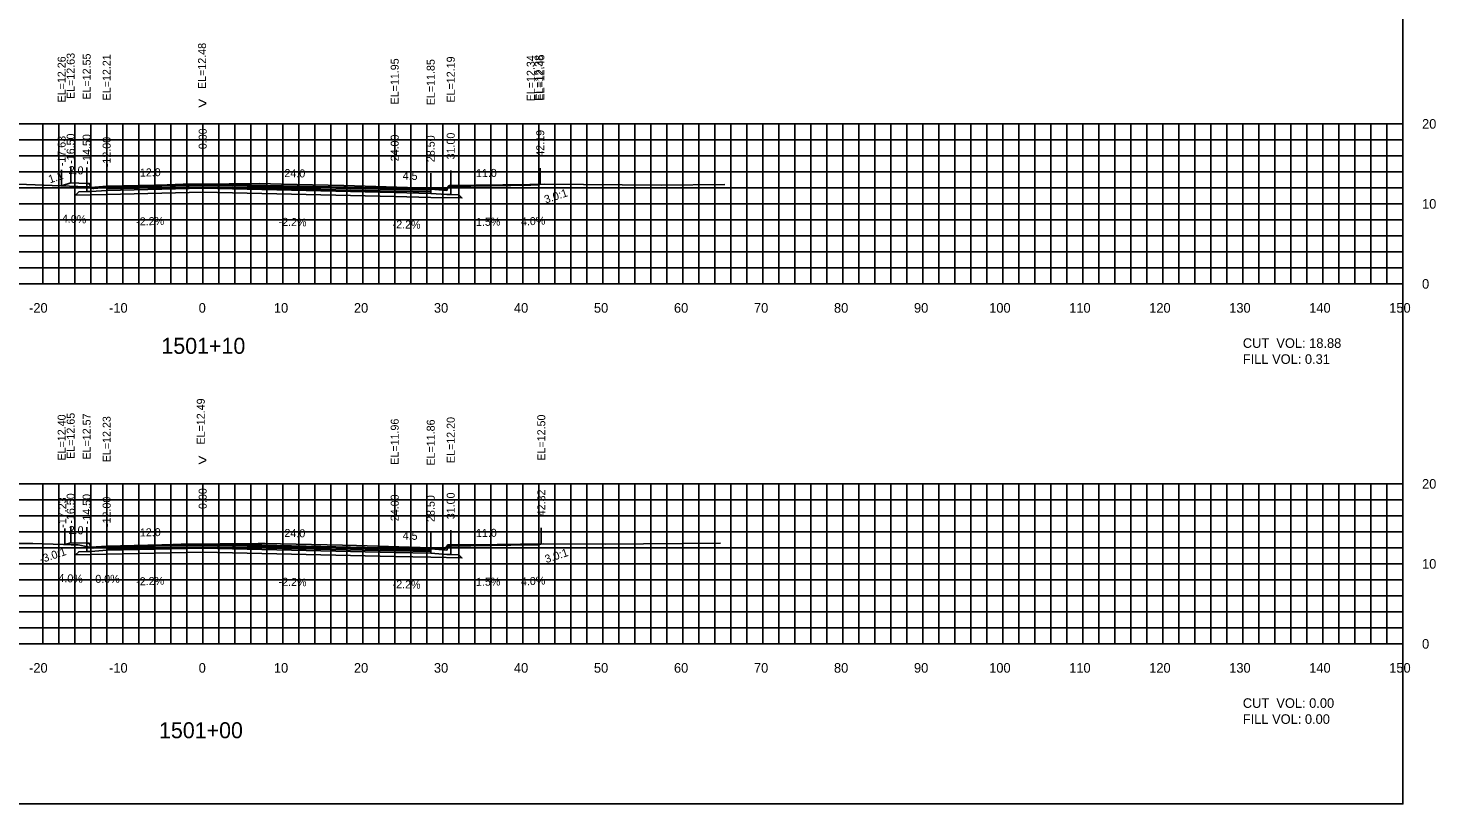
# Model space of a CAD drawing. Extents: x 1800674 to 1802785, y 250079 to 250269.
# Drawn here: x 1802269.2 to 1802445.1, y 250079.4 to 250176.4 of the extents above; entities that cross this region are included whole.
import ezdxf

# ---------------------------------------------------------------- set-up
doc = ezdxf.new("R2010")
doc.units = 0
for name, color, linetype in [('1', 7, 'Continuous'), ('10', 7, 'Continuous'), ('3', 7, 'Continuous'), ('31', 7, 'Continuous'), ('4', 7, 'Continuous'), ('60', 7, 'Continuous'), ('ANNO-TXT', 7, 'Continuous'), ('BASE', 7, 'Continuous'), ('CL-CNST', 7, 'Continuous'), ('Level 62', 7, 'Continuous'), ('LOWER BINDER', 7, 'Continuous'), ('M-ROADS', 7, 'Continuous'), ('UPPER BINDER', 7, 'Continuous'), ('WEARING', 7, 'Continuous')]:
    doc.layers.add(name, color=color, linetype=linetype)

msp = doc.modelspace()

# ---------------------------------------------------------------- linework, layer by layer
for p, q in [((1802273.37, 250156.69), (1802273.37, 250158.69)), ((1802274.5, 250157.07), (1802274.5, 250159.07)), ((1802276.5, 250156.99), (1802276.5, 250158.99)), ((1802279, 250156.65), (1802279, 250158.65)), ((1802291, 250156.91), (1802291, 250158.91)), ((1802315, 250156.38), (1802315, 250158.38)), ((1802319.5, 250156.28), (1802319.5, 250158.28)), ((1802322, 250156.62), (1802322, 250158.62)), ((1802333.19, 250156.88), (1802333.19, 250158.88)), ((1802273.77, 250111.84), (1802273.77, 250113.84)), ((1802274.5, 250112.08), (1802274.5, 250114.08)), ((1802276.5, 250112), (1802276.5, 250114)), ((1802279, 250111.66), (1802279, 250113.66)), ((1802291, 250111.92), (1802291, 250113.92)), ((1802333.32, 250111.93), (1802333.32, 250113.93)), ((1802315, 250111.39), (1802315, 250113.39)), ((1802319.5, 250111.3), (1802319.5, 250113.3)), ((1802322, 250111.64), (1802322, 250113.64))]:
    msp.add_line(p, q)
for points in [[(1802141, 250079.43), (1802441, 250079.43), (1802441, 250269.43), (1802141, 250269.43)], [(1802279, 250156.65), (1802277, 250156.49), (1802276.83, 250156.99), (1802276.5, 250156.99), (1802276.5, 250155.96), (1802277, 250155.96), (1802279, 250156.12)], [(1802319.5, 250156.28), (1802321.5, 250156.12), (1802321.67, 250156.62), (1802322, 250156.62), (1802322, 250155.59), (1802321.5, 250155.59), (1802319.5, 250155.75)], [(1802279, 250111.66), (1802277, 250111.5), (1802276.83, 250112), (1802276.5, 250112), (1802276.5, 250110.97), (1802277, 250110.97), (1802279, 250111.13)], [(1802319.5, 250111.3), (1802321.5, 250111.14), (1802321.67, 250111.64), (1802322, 250111.64), (1802322, 250110.61), (1802321.5, 250110.61), (1802319.5, 250110.77)]]:
    msp.add_lwpolyline(points, close=True)
at = {"layer": '60'}
for p, q in [((1802441, 250144.43), (1802441, 250164.43)), ((1802441.06, 250164.43), (1802441, 250164.43)), ((1802441.06, 250154.43), (1802441, 250154.43)), ((1802141, 250144.43), (1802441, 250144.43)), ((1802271, 250144.37), (1802271, 250144.43)), ((1802281, 250144.37), (1802281, 250144.43)), ((1802291, 250144.37), (1802291, 250144.43)), ((1802301, 250144.37), (1802301, 250144.43)), ((1802311, 250144.37), (1802311, 250144.43)), ((1802321, 250144.37), (1802321, 250144.43)), ((1802331, 250144.37), (1802331, 250144.43)), ((1802341, 250144.37), (1802341, 250144.43)), ((1802351, 250144.37), (1802351, 250144.43)), ((1802361, 250144.37), (1802361, 250144.43)), ((1802371, 250144.37), (1802371, 250144.43)), ((1802381, 250144.37), (1802381, 250144.43)), ((1802391, 250144.37), (1802391, 250144.43)), ((1802401, 250144.37), (1802401, 250144.43)), ((1802411, 250144.37), (1802411, 250144.43)), ((1802421, 250144.37), (1802421, 250144.43)), ((1802431, 250144.37), (1802431, 250144.43)), ((1802441, 250144.37), (1802441, 250144.43)), ((1802441.06, 250144.43), (1802441, 250144.43)), ((1802441, 250099.43), (1802441, 250119.43)), ((1802441.06, 250119.43), (1802441, 250119.43)), ((1802441.06, 250109.43), (1802441, 250109.43)), ((1802141, 250099.43), (1802441, 250099.43)), ((1802271, 250099.37), (1802271, 250099.43)), ((1802281, 250099.37), (1802281, 250099.43)), ((1802291, 250099.37), (1802291, 250099.43)), ((1802301, 250099.37), (1802301, 250099.43)), ((1802311, 250099.37), (1802311, 250099.43)), ((1802321, 250099.37), (1802321, 250099.43)), ((1802331, 250099.37), (1802331, 250099.43)), ((1802341, 250099.37), (1802341, 250099.43)), ((1802351, 250099.37), (1802351, 250099.43)), ((1802361, 250099.37), (1802361, 250099.43)), ((1802371, 250099.37), (1802371, 250099.43)), ((1802381, 250099.37), (1802381, 250099.43)), ((1802391, 250099.37), (1802391, 250099.43)), ((1802401, 250099.37), (1802401, 250099.43)), ((1802411, 250099.37), (1802411, 250099.43)), ((1802421, 250099.37), (1802421, 250099.43)), ((1802431, 250099.37), (1802431, 250099.43)), ((1802441, 250099.37), (1802441, 250099.43)), ((1802441.06, 250099.43), (1802441, 250099.43))]:
    msp.add_line(p, q, dxfattribs=at)
at = {"layer": 'BASE'}
for points in [[(1802319.5, 250155.25), (1802323.4, 250155.17), (1802323, 250155.57), (1802322, 250155.59), (1802321.5, 250155.59), (1802319.5, 250155.75), (1802315, 250155.85), (1802291, 250156.38), (1802279, 250156.12), (1802277, 250155.96), (1802276.5, 250155.96), (1802275.5, 250155.93), (1802275.1, 250155.53), (1802279, 250155.62), (1802291, 250155.88), (1802315, 250155.35)], [(1802319.5, 250110.27), (1802323.4, 250110.18), (1802323, 250110.58), (1802322, 250110.61), (1802321.5, 250110.61), (1802319.5, 250110.77), (1802315, 250110.86), (1802291, 250111.39), (1802279, 250111.13), (1802277, 250110.97), (1802276.5, 250110.97), (1802275.5, 250110.95), (1802275.1, 250110.54), (1802279, 250110.63), (1802291, 250110.89), (1802315, 250110.36)]]:
    msp.add_lwpolyline(points, close=True, dxfattribs=at)
at = {"layer": 'CL-CNST'}
for points in [[(1802273.37, 250156.69), (1802274.5, 250157.07), (1802276.5, 250156.99), (1802276.83, 250156.99), (1802277, 250156.49), (1802279, 250156.65), (1802291, 250156.91), (1802315, 250156.38), (1802319.5, 250156.28), (1802321.5, 250156.12), (1802321.67, 250156.62), (1802322, 250156.62), (1802332, 250156.77), (1802333, 250156.81), (1802333.19, 250156.88)], [(1802273.77, 250111.84), (1802274.5, 250112.08), (1802276.5, 250112), (1802276.83, 250112), (1802277, 250111.5), (1802279, 250111.66), (1802291, 250111.92), (1802315, 250111.39), (1802319.5, 250111.3), (1802321.5, 250111.14), (1802321.67, 250111.64), (1802322, 250111.64), (1802332, 250111.79), (1802333, 250111.83), (1802333.32, 250111.93)]]:
    msp.add_lwpolyline(points, dxfattribs=at)
at = {"layer": 'Level 62'}
for p, q in [((1802141, 250164.43), (1802441, 250164.43)), ((1802271, 250144.43), (1802271, 250164.43)), ((1802273, 250144.43), (1802273, 250164.43)), ((1802275, 250144.43), (1802275, 250164.43)), ((1802277, 250144.43), (1802277, 250164.43)), ((1802279, 250144.43), (1802279, 250164.43)), ((1802281, 250144.43), (1802281, 250164.43)), ((1802283, 250144.43), (1802283, 250164.43)), ((1802285, 250144.43), (1802285, 250164.43)), ((1802287, 250144.43), (1802287, 250164.43)), ((1802289, 250144.43), (1802289, 250164.43)), ((1802291, 250144.43), (1802291, 250164.43)), ((1802293, 250144.43), (1802293, 250164.43)), ((1802295, 250144.43), (1802295, 250164.43)), ((1802297, 250144.43), (1802297, 250164.43)), ((1802299, 250144.43), (1802299, 250164.43)), ((1802301, 250144.43), (1802301, 250164.43)), ((1802303, 250144.43), (1802303, 250164.43)), ((1802305, 250144.43), (1802305, 250164.43)), ((1802307, 250144.43), (1802307, 250164.43)), ((1802309, 250144.43), (1802309, 250164.43)), ((1802311, 250144.43), (1802311, 250164.43)), ((1802313, 250144.43), (1802313, 250164.43)), ((1802315, 250144.43), (1802315, 250164.43)), ((1802317, 250144.43), (1802317, 250164.43)), ((1802319, 250144.43), (1802319, 250164.43)), ((1802321, 250144.43), (1802321, 250164.43)), ((1802323, 250144.43), (1802323, 250164.43)), ((1802325, 250144.43), (1802325, 250164.43)), ((1802327, 250144.43), (1802327, 250164.43)), ((1802329, 250144.43), (1802329, 250164.43)), ((1802331, 250144.43), (1802331, 250164.43)), ((1802333, 250144.43), (1802333, 250164.43)), ((1802335, 250144.43), (1802335, 250164.43)), ((1802337, 250144.43), (1802337, 250164.43)), ((1802339, 250144.43), (1802339, 250164.43)), ((1802341, 250144.43), (1802341, 250164.43)), ((1802343, 250144.43), (1802343, 250164.43)), ((1802345, 250144.43), (1802345, 250164.43)), ((1802347, 250144.43), (1802347, 250164.43)), ((1802349, 250144.43), (1802349, 250164.43)), ((1802351, 250144.43), (1802351, 250164.43)), ((1802353, 250144.43), (1802353, 250164.43)), ((1802355, 250144.43), (1802355, 250164.43)), ((1802357, 250144.43), (1802357, 250164.43)), ((1802359, 250144.43), (1802359, 250164.43)), ((1802361, 250144.43), (1802361, 250164.43)), ((1802363, 250144.43), (1802363, 250164.43)), ((1802365, 250144.43), (1802365, 250164.43)), ((1802367, 250144.43), (1802367, 250164.43)), ((1802369, 250144.43), (1802369, 250164.43)), ((1802371, 250144.43), (1802371, 250164.43)), ((1802373, 250144.43), (1802373, 250164.43)), ((1802375, 250144.43), (1802375, 250164.43)), ((1802377, 250144.43), (1802377, 250164.43)), ((1802379, 250144.43), (1802379, 250164.43)), ((1802381, 250144.43), (1802381, 250164.43)), ((1802383, 250144.43), (1802383, 250164.43)), ((1802385, 250144.43), (1802385, 250164.43)), ((1802387, 250144.43), (1802387, 250164.43)), ((1802389, 250144.43), (1802389, 250164.43)), ((1802391, 250144.43), (1802391, 250164.43)), ((1802393, 250144.43), (1802393, 250164.43)), ((1802395, 250144.43), (1802395, 250164.43)), ((1802397, 250144.43), (1802397, 250164.43)), ((1802399, 250144.43), (1802399, 250164.43)), ((1802401, 250144.43), (1802401, 250164.43)), ((1802403, 250144.43), (1802403, 250164.43)), ((1802405, 250144.43), (1802405, 250164.43)), ((1802407, 250144.43), (1802407, 250164.43)), ((1802409, 250144.43), (1802409, 250164.43)), ((1802411, 250144.43), (1802411, 250164.43)), ((1802413, 250144.43), (1802413, 250164.43)), ((1802415, 250144.43), (1802415, 250164.43)), ((1802417, 250144.43), (1802417, 250164.43)), ((1802419, 250144.43), (1802419, 250164.43)), ((1802421, 250144.43), (1802421, 250164.43)), ((1802423, 250144.43), (1802423, 250164.43)), ((1802425, 250144.43), (1802425, 250164.43)), ((1802427, 250144.43), (1802427, 250164.43)), ((1802429, 250144.43), (1802429, 250164.43)), ((1802431, 250144.43), (1802431, 250164.43)), ((1802433, 250144.43), (1802433, 250164.43)), ((1802435, 250144.43), (1802435, 250164.43)), ((1802437, 250144.43), (1802437, 250164.43)), ((1802439, 250144.43), (1802439, 250164.43)), ((1802441, 250144.43), (1802441, 250164.43)), ((1802141, 250162.43), (1802441, 250162.43)), ((1802141, 250160.43), (1802441, 250160.43)), ((1802141, 250158.43), (1802441, 250158.43)), ((1802141, 250156.43), (1802441, 250156.43)), ((1802141, 250154.43), (1802441, 250154.43)), ((1802141, 250152.43), (1802441, 250152.43)), ((1802141, 250150.43), (1802441, 250150.43)), ((1802141, 250148.43), (1802441, 250148.43)), ((1802141, 250146.43), (1802441, 250146.43)), ((1802141, 250144.43), (1802441, 250144.43)), ((1802141, 250119.43), (1802441, 250119.43)), ((1802271, 250099.43), (1802271, 250119.43)), ((1802273, 250099.43), (1802273, 250119.43)), ((1802275, 250099.43), (1802275, 250119.43)), ((1802277, 250099.43), (1802277, 250119.43)), ((1802279, 250099.43), (1802279, 250119.43)), ((1802281, 250099.43), (1802281, 250119.43)), ((1802283, 250099.43), (1802283, 250119.43)), ((1802285, 250099.43), (1802285, 250119.43)), ((1802287, 250099.43), (1802287, 250119.43)), ((1802289, 250099.43), (1802289, 250119.43)), ((1802291, 250099.43), (1802291, 250119.43)), ((1802293, 250099.43), (1802293, 250119.43)), ((1802295, 250099.43), (1802295, 250119.43)), ((1802297, 250099.43), (1802297, 250119.43)), ((1802299, 250099.43), (1802299, 250119.43)), ((1802301, 250099.43), (1802301, 250119.43)), ((1802303, 250099.43), (1802303, 250119.43)), ((1802305, 250099.43), (1802305, 250119.43)), ((1802307, 250099.43), (1802307, 250119.43)), ((1802309, 250099.43), (1802309, 250119.43)), ((1802311, 250099.43), (1802311, 250119.43)), ((1802313, 250099.43), (1802313, 250119.43)), ((1802315, 250099.43), (1802315, 250119.43)), ((1802317, 250099.43), (1802317, 250119.43)), ((1802319, 250099.43), (1802319, 250119.43)), ((1802321, 250099.43), (1802321, 250119.43)), ((1802323, 250099.43), (1802323, 250119.43)), ((1802325, 250099.43), (1802325, 250119.43)), ((1802327, 250099.43), (1802327, 250119.43)), ((1802329, 250099.43), (1802329, 250119.43)), ((1802331, 250099.43), (1802331, 250119.43)), ((1802333, 250099.43), (1802333, 250119.43)), ((1802335, 250099.43), (1802335, 250119.43)), ((1802337, 250099.43), (1802337, 250119.43)), ((1802339, 250099.43), (1802339, 250119.43)), ((1802341, 250099.43), (1802341, 250119.43)), ((1802343, 250099.43), (1802343, 250119.43)), ((1802345, 250099.43), (1802345, 250119.43)), ((1802347, 250099.43), (1802347, 250119.43)), ((1802349, 250099.43), (1802349, 250119.43)), ((1802351, 250099.43), (1802351, 250119.43)), ((1802353, 250099.43), (1802353, 250119.43)), ((1802355, 250099.43), (1802355, 250119.43)), ((1802357, 250099.43), (1802357, 250119.43)), ((1802359, 250099.43), (1802359, 250119.43)), ((1802361, 250099.43), (1802361, 250119.43)), ((1802363, 250099.43), (1802363, 250119.43)), ((1802365, 250099.43), (1802365, 250119.43)), ((1802367, 250099.43), (1802367, 250119.43)), ((1802369, 250099.43), (1802369, 250119.43)), ((1802371, 250099.43), (1802371, 250119.43)), ((1802373, 250099.43), (1802373, 250119.43)), ((1802375, 250099.43), (1802375, 250119.43)), ((1802377, 250099.43), (1802377, 250119.43)), ((1802379, 250099.43), (1802379, 250119.43)), ((1802381, 250099.43), (1802381, 250119.43)), ((1802383, 250099.43), (1802383, 250119.43)), ((1802385, 250099.43), (1802385, 250119.43)), ((1802387, 250099.43), (1802387, 250119.43)), ((1802389, 250099.43), (1802389, 250119.43)), ((1802391, 250099.43), (1802391, 250119.43)), ((1802393, 250099.43), (1802393, 250119.43)), ((1802395, 250099.43), (1802395, 250119.43)), ((1802397, 250099.43), (1802397, 250119.43)), ((1802399, 250099.43), (1802399, 250119.43)), ((1802401, 250099.43), (1802401, 250119.43)), ((1802403, 250099.43), (1802403, 250119.43)), ((1802405, 250099.43), (1802405, 250119.43)), ((1802407, 250099.43), (1802407, 250119.43)), ((1802409, 250099.43), (1802409, 250119.43)), ((1802411, 250099.43), (1802411, 250119.43)), ((1802413, 250099.43), (1802413, 250119.43)), ((1802415, 250099.43), (1802415, 250119.43)), ((1802417, 250099.43), (1802417, 250119.43)), ((1802419, 250099.43), (1802419, 250119.43)), ((1802421, 250099.43), (1802421, 250119.43)), ((1802423, 250099.43), (1802423, 250119.43)), ((1802425, 250099.43), (1802425, 250119.43)), ((1802427, 250099.43), (1802427, 250119.43)), ((1802429, 250099.43), (1802429, 250119.43)), ((1802431, 250099.43), (1802431, 250119.43)), ((1802433, 250099.43), (1802433, 250119.43)), ((1802435, 250099.43), (1802435, 250119.43)), ((1802437, 250099.43), (1802437, 250119.43)), ((1802439, 250099.43), (1802439, 250119.43)), ((1802441, 250099.43), (1802441, 250119.43)), ((1802141, 250117.43), (1802441, 250117.43)), ((1802141, 250115.43), (1802441, 250115.43)), ((1802141, 250113.43), (1802441, 250113.43)), ((1802141, 250111.43), (1802441, 250111.43)), ((1802141, 250109.43), (1802441, 250109.43)), ((1802141, 250107.43), (1802441, 250107.43)), ((1802141, 250105.43), (1802441, 250105.43)), ((1802141, 250103.43), (1802441, 250103.43)), ((1802141, 250101.43), (1802441, 250101.43)), ((1802141, 250099.43), (1802441, 250099.43))]:
    msp.add_line(p, q, dxfattribs=at)
at = {"layer": 'LOWER BINDER'}
for points in [[(1802279, 250156.12), (1802279, 250156.31), (1802291, 250156.57), (1802315, 250156.04), (1802319.5, 250155.94), (1802319.5, 250155.75), (1802315, 250155.85), (1802291, 250156.38)], [(1802279, 250111.13), (1802279, 250111.32), (1802291, 250111.58), (1802315, 250111.05), (1802319.5, 250110.96), (1802319.5, 250110.77), (1802315, 250110.86), (1802291, 250111.39)]]:
    msp.add_lwpolyline(points, close=True, dxfattribs=at)
at = {"layer": 'M-ROADS'}
for points in [[(1802266.87, 250156.92), (1802276.48, 250156.58), (1802276.56, 250156.58), (1802276.63, 250156.57), (1802276.73, 250156.55), (1802277.3, 250156.37), (1802277.31, 250156.37), (1802277.34, 250156.36), (1802277.41, 250156.36), (1802278.86, 250156.47), (1802279.77, 250156.51), (1802281.52, 250156.59), (1802288.57, 250156.89), (1802290.52, 250156.9), (1802298.12, 250156.97), (1802300.84, 250156.91), (1802308.62, 250156.74), (1802317.95, 250156.43), (1802319.61, 250156.37), (1802321.22, 250156.25), (1802321.38, 250156.24), (1802321.42, 250156.28), (1802321.8, 250156.71), (1802331.89, 250156.86), (1802333.73, 250156.88), (1802348.32, 250156.77), (1802356.27, 250156.86)], [(1802255.34, 250111.96), (1802269.75, 250111.98), (1802273.59, 250111.84), (1802274.55, 250111.83), (1802275.42, 250111.81), (1802276.63, 250111.56), (1802276.9, 250111.47), (1802277, 250111.52), (1802277.3, 250111.4), (1802278.12, 250111.45), (1802278.91, 250111.51), (1802288.32, 250111.9), (1802288.35, 250111.9), (1802288.4, 250111.9), (1802297.94, 250111.99), (1802298.81, 250111.97), (1802308.48, 250111.77), (1802310.22, 250111.71), (1802319.5, 250111.42), (1802320.38, 250111.36), (1802321.26, 250111.31), (1802321.54, 250111.7), (1802321.62, 250111.79), (1802324.94, 250111.83), (1802333.61, 250111.94), (1802341.32, 250111.88), (1802355.7, 250112.03)]]:
    msp.add_lwpolyline(points, dxfattribs=at)
at = {"layer": 'UPPER BINDER'}
for points in [[(1802291, 250156.57), (1802279, 250156.31), (1802279, 250156.5), (1802291, 250156.76), (1802315, 250156.23), (1802319.5, 250156.13), (1802319.5, 250155.75), (1802319.5, 250155.94), (1802315, 250156.04)], [(1802291, 250111.58), (1802279, 250111.32), (1802279, 250111.51), (1802291, 250111.77), (1802315, 250111.24), (1802319.5, 250111.15), (1802319.5, 250110.77), (1802319.5, 250110.96), (1802315, 250111.05)]]:
    msp.add_lwpolyline(points, close=True, dxfattribs=at)
at = {"layer": 'WEARING'}
for points in [[(1802319.5, 250156.13), (1802319.5, 250156.28), (1802315, 250156.38), (1802291, 250156.91), (1802279, 250156.65), (1802279, 250156.5), (1802291, 250156.76), (1802315, 250156.23)], [(1802319.5, 250111.15), (1802319.5, 250111.3), (1802315, 250111.39), (1802291, 250111.92), (1802279, 250111.66), (1802279, 250111.51), (1802291, 250111.77), (1802315, 250111.24)]]:
    msp.add_lwpolyline(points, close=True, dxfattribs=at)

# ---------------------------------------------------------------- texts
for s, p in [('3.0:1', (1802333.88, 250154.47)), ('-3.0:1', (1802270.79, 250109.49)), ('3.0:1', (1802333.95, 250109.51))]:
    msp.add_text(s, height=1, rotation=18.4349).set_placement(p)
at = {"layer": '1'}
for s, p in [('1501+10', (1802285.84, 250135.69)), ('1501+00', (1802285.54, 250087.63))]:
    msp.add_text(s, height=2, dxfattribs=at).set_placement(p)
at = {"layer": '10'}
for s, p in [('-20', (1802269.3, 250140.83)), ('-10', (1802279.3, 250140.83)), ('0', (1802290.5, 250140.83)), ('10', (1802299.9, 250140.83)), ('20', (1802309.9, 250140.83)), ('30', (1802319.9, 250140.83)), ('40', (1802329.9, 250140.83)), ('50', (1802339.9, 250140.83)), ('60', (1802349.9, 250140.83)), ('70', (1802359.9, 250140.83)), ('80', (1802369.9, 250140.83)), ('90', (1802379.9, 250140.83)), ('100', (1802389.3, 250140.83)), ('110', (1802399.3, 250140.83)), ('120', (1802409.3, 250140.83)), ('130', (1802419.3, 250140.83)), ('140', (1802429.3, 250140.83)), ('150', (1802439.3, 250140.83)), ('-20', (1802269.3, 250095.83)), ('-10', (1802279.3, 250095.83)), ('0', (1802290.5, 250095.83)), ('10', (1802299.9, 250095.83)), ('20', (1802309.9, 250095.83)), ('30', (1802319.9, 250095.83)), ('40', (1802329.9, 250095.83)), ('50', (1802339.9, 250095.83)), ('60', (1802349.9, 250095.83)), ('70', (1802359.9, 250095.83)), ('80', (1802369.9, 250095.83)), ('90', (1802379.9, 250095.83)), ('100', (1802389.3, 250095.83)), ('110', (1802399.3, 250095.83)), ('120', (1802409.3, 250095.83)), ('130', (1802419.3, 250095.83)), ('140', (1802429.3, 250095.83)), ('150', (1802439.3, 250095.83))]:
    msp.add_text(s, height=1.2, dxfattribs=at).set_placement(p)
at = {"layer": '3'}
for s, p in [('EL=12.48', (1802291.42, 250168.79)), ('EL=12.26', (1802273.87, 250167.11)), ('EL=12.63', (1802275, 250167.54)), ('EL=12.55', (1802277, 250167.46)), ('EL=12.21', (1802279.5, 250167.37)), ('EL=11.95', (1802315.5, 250166.86)), ('EL=11.85', (1802320, 250166.76)), ('EL=12.19', (1802322.5, 250167.1)), ('EL=12.34', (1802332.5, 250167.25)), ('EL=12.38', (1802333.5, 250167.29)), ('EL=12.45', (1802333.69, 250167.35)), ('-16.50', (1802275, 250159.44)), ('-14.50', (1802277, 250159.36)), ('0.00', (1802291.5, 250161.27)), ('24.00', (1802315.5, 250159.75)), ('28.50', (1802320, 250159.65)), ('31.00', (1802322.5, 250159.99)), ('42.19', (1802333.69, 250160.33)), ('-17.63', (1802273.87, 250159.14)), ('-12.00', (1802279.5, 250159.02)), ('EL=12.49', (1802291.26, 250124.35)), ('EL=12.40', (1802273.87, 250122.35)), ('EL=12.65', (1802275, 250122.55)), ('EL=12.57', (1802277, 250122.47)), ('EL=12.23', (1802279.5, 250122.13)), ('EL=12.20', (1802322.5, 250122.03)), ('EL=12.50', (1802333.82, 250122.33)), ('EL=11.96', (1802315.5, 250121.82)), ('EL=11.86', (1802320, 250121.72)), ('-17.23', (1802273.96, 250113.95)), ('-16.50', (1802275, 250114.46)), ('-14.50', (1802277, 250114.38)), ('-12.00', (1802279.5, 250114.04)), ('0.00', (1802291.5, 250116.29)), ('24.00', (1802315.5, 250114.77)), ('28.50', (1802320, 250114.67)), ('31.00', (1802322.5, 250115.01)), ('42.32', (1802333.82, 250115.38))]:
    msp.add_text(s, height=1, rotation=90, dxfattribs=at).set_placement(p)
at = {"layer": '31'}
for s, p in [('20', (1802443.4, 250163.83)), ('10', (1802443.4, 250153.83)), ('0', (1802443.4, 250143.83)), ('20', (1802443.4, 250118.83)), ('10', (1802443.4, 250108.83)), ('0', (1802443.4, 250098.83))]:
    msp.add_text(s, height=1.2, dxfattribs=at).set_placement(p)
at = {"layer": '4'}
for s, rotation, p in [('1.1', 18.4349, (1802271.9, 250156.99)), ('2.0', 357.7094, (1802274.23, 250158.18)), ('12.0', 1.2603, (1802283.16, 250157.84)), ('24.0', 358.7397, (1802301.21, 250157.79)), ('4.5', 358.7397, (1802315.99, 250157.46)), ('11.0', 0.8594, (1802325.16, 250157.77)), ('4.0%', 357.7094, (1802273.39, 250152.11)), ('-2.2%', 1.2603, (1802282.7, 250151.73)), ('-2.2%', 358.7397, (1802300.48, 250151.7)), ('-2.2%', 358.7397, (1802314.73, 250151.39)), ('1.5%', 0.8594, (1802325.16, 250151.67)), ('4.0%', 2.2906, (1802330.79, 250151.72)), ('2.0', 357.7094, (1802274.23, 250113.19)), ('12.0', 1.2603, (1802283.16, 250112.85)), ('24.0', 358.7397, (1802301.21, 250112.8)), ('11.0', 0.8594, (1802325.16, 250112.78)), ('4.5', 358.7397, (1802315.99, 250112.47)), ('4.0%', 357.7094, (1802272.95, 250107.18)), ('-2.2%', 1.2603, (1802282.7, 250106.74)), ('-2.2%', 358.7397, (1802300.48, 250106.71)), ('-2.2%', 358.7397, (1802314.73, 250106.4)), ('1.5%', 0.8594, (1802325.16, 250106.68)), ('4.0%', 2.2906, (1802330.79, 250106.73))]:
    msp.add_text(s, height=1, rotation=rotation, dxfattribs=at).set_placement(p)
msp.add_text('0.0%', height=1, dxfattribs=at).set_placement((1802277.58, 250107.06))
at = {"layer": '60'}
for p in [(1802290.39, 250166.29), (1802290.39, 250121.68)]:
    msp.add_text('>', height=1.5, dxfattribs=at).set_placement(p)
at = {"layer": 'ANNO-TXT'}
for s, p in [('CUT  VOL: 18.88', (1802421, 250136.43)), ('FILL VOL: 0.31', (1802421, 250134.43)), ('CUT  VOL: 0.00', (1802421, 250091.43)), ('FILL VOL: 0.00', (1802421, 250089.43))]:
    msp.add_text(s, height=1.2, dxfattribs=at).set_placement(p)

doc.saveas('drawing.dxf')
